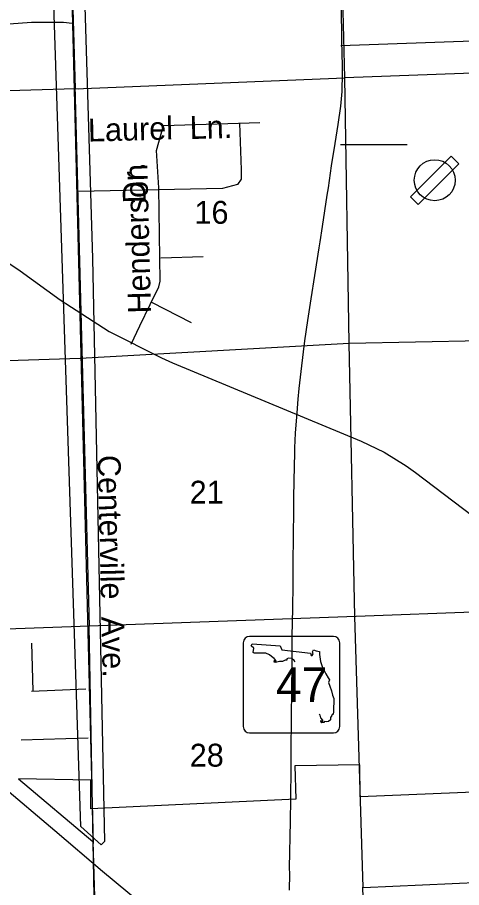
# Model space of a CAD drawing. Extents: x 2480962 to 2688785, y 277103 to 599240.
# Drawn here: x 2528890 to 2537628, y 342289 to 359405 of the extents above; entities that cross this region are included whole.
import ezdxf

# ---------------------------------------------------------------- set-up
doc = ezdxf.new("R2010")
doc.units = 0
for name, color, linetype in [('Airports Landing Strip or Private Airport', 7, 'Continuous'), ('Cities Incorporated Area', 7, 'Continuous'), ('County Routes Highway Center Lines', 7, 'Continuous'), ('Level 31', 7, 'Continuous'), ('Local Roads Improved', 7, 'Continuous'), ('Local Roads Paved', 7, 'Continuous'), ('Local Roads Related Text', 7, 'Continuous'), ('Local Roads Unimproved', 7, 'Continuous'), ('Roadshields State Highways', 7, 'Continuous'), ('Section Lines', 7, 'Continuous'), ('Section Numbers', 7, 'Continuous'), ('State Routes Highway Center Lines', 7, 'Continuous'), ('Uninventoried Roads and Features', 7, 'Continuous'), ('US Routes Highway Center Lines', 7, 'Continuous')]:
    doc.layers.add(name, color=color, linetype=linetype)

msp = doc.modelspace()

# ---------------------------------------------------------------- linework, layer by layer
at = {"layer": 'Airports Landing Strip or Private Airport'}
msp.add_lwpolyline([(2537425.116, 356677.432), (2536625.118, 355877.434), (2536776.455, 355725.328), (2537575.116, 356527.432)], close=True, dxfattribs=at)
msp.add_circle((2537100.117, 356202.433), 403.112, dxfattribs=at)
at = {"layer": 'Cities Incorporated Area'}
for p, q in [((2535626.728, 344703.544), (2534346.559, 344681.481)), ((2534346.559, 344681.481), (2534368.366, 344025.756)), ((2535632.681, 344073.191), (2535626.728, 344703.544)), ((2528911.864, 344426.541), (2530373.899, 343195.115)), ((2530335.519, 344398.649), (2528911.864, 344426.541)), ((2530337.631, 343840.335), (2530335.519, 344398.649)), ((2538300.981, 344185.913), (2535632.681, 344073.191)), ((2534368.366, 344025.756), (2530337.631, 343840.335)), ((2530373.899, 343195.115), (2530586.694, 336026.565))]:
    msp.add_line(p, q, dxfattribs=at)
at = {"layer": 'County Routes Highway Center Lines'}
for p, q in [((2526057.855, 356379.666), (2528945.378, 354417.365)), ((2528945.378, 354417.365), (2529729.563, 353850.925)), ((2531942.751, 352613.131), (2535652.661, 351069.358)), ((2536720.945, 350454.267), (2543904.478, 344987.586))]:
    msp.add_line(p, q, dxfattribs=at)
for points in [[(2529729.563, 353850.925), (2530696.174, 353226.993), (2531722.709, 352707.52), (2531942.751, 352613.131)], [(2535652.661, 351069.358), (2536108.167, 350851.181), (2536538.372, 350586.586), (2536720.945, 350454.267)]]:
    msp.add_lwpolyline(points, dxfattribs=at)
at = {"layer": 'Level 31'}
msp.add_lwpolyline([(2529508.281, 362652.438), (2529508.281, 363149.655), (2530104.941, 363282.246), (2530370.123, 354663.824), (2530602.158, 343194.694), (2530535.862, 343128.398), (2530138.089, 343493.024)], close=True, dxfattribs=at)
at = {"layer": 'Local Roads Improved'}
for p, q in [((2530384.996, 343156.556), (2529882.862, 363307.677)), ((2531709.631, 354676.862), (2532546.289, 354699.784)), ((2531527.393, 353801.506), (2532305.606, 353404.685)), ((2530237.788, 346192.502), (2529169.166, 346142.633)), ((2530280.533, 345230.742), (2528962.566, 345187.997))]:
    msp.add_line(p, q, dxfattribs=at)
for points in [[(2533256.874, 357324.366), (2533291.257, 356407.482), (2533291.257, 356224.105), (2533222.491, 356120.955), (2532924.503, 356040.728), (2530082.161, 355983.423)], [(2531504.765, 353760.492), (2531675.248, 354103.809), (2531698.17, 354218.42), (2531675.248, 356052.189), (2531629.404, 356785.697), (2531766.937, 357278.522), (2533658.011, 357335.827)]]:
    msp.add_lwpolyline(points, dxfattribs=at)
at = {"layer": 'Local Roads Paved'}
for points in [[(2525936.382, 359231.297), (2526333.905, 359217.835), (2526704.092, 359228.565), (2527144.025, 359255.39), (2527380.086, 359298.311), (2527583.958, 359309.041), (2527707.354, 359298.311), (2527986.335, 359260.755), (2528276.047, 359271.486), (2528726.71, 359276.851), (2529166.643, 359309.041), (2529461.72, 359309.041), (2529794.352, 359309.041), (2529966.033, 359292.946), (2529966.033, 359292.946)], [(2531125.118, 352980.626), (2531297.033, 353335.919), (2531503.332, 353759.978)]]:
    msp.add_lwpolyline(points, dxfattribs=at)
at = {"layer": 'Local Roads Unimproved'}
for p, q in [((2535252.854, 358850.223), (2540500.953, 359042.405)), ((2535248.477, 356904.717), (2536560.585, 356905.75)), ((2529197.663, 346156.881), (2529176.29, 347097.268))]:
    msp.add_line(p, q, dxfattribs=at)
at = {"layer": 'Roadshields State Highways'}
for p, q in [((2535107.322, 347229.713), (2533457.322, 347229.713)), ((2533332.322, 347104.713), (2533332.322, 345454.713)), ((2535232.322, 345454.713), (2535232.322, 347104.713)), ((2533457.322, 345329.713), (2535107.322, 345329.713))]:
    msp.add_line(p, q, dxfattribs=at)
for points in [[(2534351.961, 346730.615), (2534332.259, 346755.959), (2534289.405, 346792.24), (2534220.18, 346802.135), (2534190.511, 346788.942), (2534187.215, 346759.257), (2534157.547, 346762.556), (2534104.803, 346732.871), (2534045.467, 346732.871), (2533969.648, 346713.081), (2533943.277, 346719.678), (2533946.573, 346762.556), (2533963.056, 346732.871), (2533979.538, 346749.363), (2533943.277, 346792.24), (2533887.237, 346835.118), (2533850.976, 346864.802), (2533778.454, 346897.785), (2533702.635, 346901.083), (2533547.701, 346897.785), (2533524.626, 346914.276), (2533537.812, 347000.032), (2533491.662, 347042.909), (2533508.144, 347082.489)], [(2533508.144, 347082.489), (2534061.949, 347042.909), (2534091.618, 346963.751), (2534655.312, 346901.083), (2534668.498, 346854.907), (2534691.573, 346854.907), (2534708.056, 346887.89), (2534698.166, 346927.47), (2534717.945, 346967.049), (2534767.392, 346943.961), (2534833.321, 346934.066), (2534833.321, 346871.399), (2534853.1, 346736.169), (2534886.065, 346640.519), (2534955.29, 346492.097), (2535001.441, 346412.938), (2535027.812, 346376.657), (2535008.034, 346320.586), (2535034.405, 346251.323), (2535067.37, 346155.673), (2535090.445, 346076.514), (2535116.817, 346007.25), (2535116.817, 345944.583), (2535110.224, 345819.248), (2535106.928, 345746.686), (2535103.631, 345690.615), (2535090.445, 345707.107), (2535073.963, 345670.826), (2535050.888, 345631.246), (2535050.888, 345585.07), (2535011.33, 345555.386), (2534968.476, 345548.789), (2534932.215, 345555.386), (2534919.029, 345535.596), (2534876.175, 345529), (2534856.397, 345565.281), (2534866.286, 345581.772), (2534879.472, 345558.684), (2534895.954, 345552.088), (2534895.954, 345581.772), (2534859.693, 345624.65), (2534846.507, 345677.422), (2534824.011, 345701.977)]]:
    msp.add_lwpolyline(points, dxfattribs=at)
for centre, start, end in [((2533457.322, 347104.713), 90, 180), ((2535107.322, 347104.713), 0, 90), ((2533457.322, 345454.713), 180, 270), ((2535107.322, 345454.713), 270, 0)]:
    msp.add_arc(centre, 125, start, end, dxfattribs=at)
at = {"layer": 'Section Lines'}
for p, q in [((2535333.041, 358215.065), (2535193, 363464.757)), ((2529882.862, 363307.677), (2530299.222, 347432.116)), ((2529883.002, 363302.298), (2530023.829, 357999.933)), ((2540562.287, 358405.917), (2535333.044, 358214.934)), ((2530023.829, 357999.933), (2535333.041, 358215.065)), ((2535415.441, 352999.829), (2535333.041, 358215.056)), ((2530023.829, 357999.933), (2524624.479, 357827.747)), ((2530095.765, 357991.358), (2530023.829, 357999.933)), ((2530126.711, 352704.228), (2535415.441, 352999.829)), ((2535415.44, 352999.829), (2540714.799, 353097.131)), ((2535525.944, 347622.774), (2535415.44, 352999.829)), ((2524736.354, 352529.608), (2530126.711, 352704.228)), ((2540800.49, 347810.679), (2535556.41, 347623.885)), ((2535556.41, 347623.885), (2524910.177, 347235.537)), ((2535692.862, 342288.545), (2535525.944, 347622.774)), ((2530402.655, 342113.946), (2530299.222, 347432.116)), ((2535692.862, 342288.545), (2540978.199, 342525.59)), ((2535824.216, 337028.156), (2535687.337, 342295.078))]:
    msp.add_line(p, q, dxfattribs=at)
at = {"layer": 'State Routes Highway Center Lines'}
msp.add_lwpolyline([(2535242.823, 359995.021), (2535267.718, 359138.613), (2535266.059, 358947.747), (2535276.017, 358446.516), (2535277.677, 358214.158), (2535272.697, 358041.548), (2535269.378, 357948.605), (2535244.482, 357659.816), (2535194.691, 357298), (2535134.942, 356921.247), (2535065.234, 356483.085), (2535002.166, 356049.902), (2534978.93, 355910.487), (2534885.986, 355293.077), (2534837.855, 354991.01), (2534819.598, 354869.852), (2534736.613, 354327.128), (2534661.926, 353872.369), (2534595.538, 353445.825), (2534535.788, 353044.176), (2534509.233, 352825.095), (2534462.761, 352436.724), (2534424.588, 352103.123), (2534406.331, 351894.001), (2534386.415, 351628.448), (2534354.881, 351225.139), (2534343.263, 350941.33), (2534343.263, 350841.748), (2534326.666, 350299.024), (2534321.686, 349950.486), (2534318.367, 349807.751), (2534315.048, 349104.036), (2534310.068, 348762.137), (2534305.089, 348250.948), (2534298.451, 347777.932), (2534291.812, 347233.549), (2534290.152, 346797.046), (2534288.492, 346722.359), (2534280.194, 346126.525), (2534275.215, 345695.002), (2534271.895, 344908.302), (2534268.576, 344641.089), (2534261.937, 344026.998), (2534256.958, 343593.815), (2534238.701, 342674.339), (2534240.361, 342556.5), (2534235.382, 342236.176)], dxfattribs=at)
at = {"layer": 'US Routes Highway Center Lines'}
msp.add_lwpolyline([(2528558.689, 344318.278), (2529623.03, 343411.088), (2530565.936, 342611.047), (2531558.844, 341782.433)], dxfattribs=at)

# ---------------------------------------------------------------- texts
at = {"layer": 'Local Roads Related Text'}
msp.add_text('Centerville  Ave.', height=450, rotation=271.3269444, dxfattribs=at).set_placement((2530467.713, 350793.001))
at = {"layer": 'Roadshields State Highways'}
msp.add_text('47', height=680, dxfattribs=at).set_placement((2533975.657, 345939.716))
at = {"layer": 'Section Numbers'}
for s, rotation, p in [('16', 0.0672528, (2532373.866, 355344.777)), ('21', 0.0672361, (2532278.633, 349840.662)), ('28', 0.0672222, (2532280.621, 344667.268))]:
    msp.add_text(s, height=450, rotation=rotation, dxfattribs=at).set_placement(p)
at = {"layer": 'Uninventoried Roads and Features'}
for s, rotation, p in [('Laurel', 1.5003833, (2530283.509, 356961.478)), ('Ln.', 1.5003833, (2532283.66, 357011.707)), ('Dr.', 91.7325472, (2531417.489, 355754.129)), ('Henderson', 91.4835028, (2531519.791, 353584.973))]:
    msp.add_text(s, height=450, rotation=rotation, dxfattribs=at).set_placement(p)

doc.saveas('drawing.dxf')
